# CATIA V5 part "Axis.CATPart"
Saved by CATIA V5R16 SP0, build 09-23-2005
Part number: Axis
Bounding box of the stored display mesh (mm): x -19.5 to 19.5, y 0 to 171, z -19.486 to 19.486
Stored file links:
  C:\V5_education\CATIA Data\ASD\Power Transmission Gear Assembly\Assembly Data\Axis.CATPart
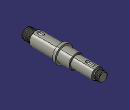
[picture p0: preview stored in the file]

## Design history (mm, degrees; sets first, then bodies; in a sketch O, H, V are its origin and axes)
Set1 "Reference Data"
  Point1 "Center Point": (0, 0, 0)
  Plane1: type Offset, RefPlane zx-plane, Offset 18
  Plane2: type Offset, RefPlane zx-plane, Offset -160, reversed
Body1 (main body)
  Body2
    Sketch1 on yz-plane, origin (0, 0, 0), H (0, 1, 0), V (0, 0, 1)
      line L1 (0, 0) -> (0, 12)
      line L2 (0, 12) -> (18, 12)
      line L3 (18, 12) -> (18, 11)
      line L4 (18, 11) -> (20, 11)
      line L5 (20, 11) -> (20, 15)
      line L6 (20, 15) -> (77, 15)
      line L7 (77, 15) -> (77, 19.5)
      point P7 (77, 19.5)
      line L8 (77, 19.5) -> (83, 19.5)
      line L9 (83, 19.5) -> (83, 15.5)
      line L10 (83, 15.5) -> (111, 15.5)
      line L11 (111, 15.5) -> (111, 12.5)
      line L12 (111, 12.5) -> (158, 12.5)
      line L13 (158, 12.5) -> (158, 9)
      line L14 (158, 9) -> (160, 9)
      line L15 (160, 9) -> (160, 10)
      line L16 (160, 10) -> (171, 10)
      line L17 (171, 10) -> (171, 0)
      point P17 (171, 0)
      axis line L18 (0, 0) -> (171, 0)
      distance L2 H = 12
      distance L18 L4 = 11
      distance L18 L6 = 15
      distance L8 L18 = 19.5
      distance L12 L18 = 12.5
      distance L16 L18 = 10
      distance L17 L13 = 13
      distance L17 L11 = 60
      distance L9 L11 = 28
      distance L9 P7 = 6
      distance L7 L1 = 77
      distance L5 L1 = 20
      distance L5 L3 = 2
      distance L15 L13 = 2
      distance L14 L18 = 9
      distance L10 L18 = 15.5
      vertical: L1 V, L3 V, L5 V, L7 V, L9 V, L11 V, L13 V, L15 V, L17 V
      horizontal: L2 H, L4 H, L6 H, L8 H, L10 H, L12 H, L14 H, L16 H, L18 H
      coincidence: P17 H
    Shaft1: profile Sketch1, axis Sketch1.L18, angle 360
    Chamfer1: length 1, angle 45, on face of Shaft1 from Sketch1.L17; face of Shaft1 from Sketch1.L1
    Body3
      Sketch2 on xy-plane, origin (0, 0, 0), H (0, 1, 0), V (-1, 0, 0)
        construction line L1 (28, 0) -> (35, 0)
        point P1 (28, 0)
        line L2 (28, 4) -> (35, 4)
        line L3 (35, -4) -> (28, -4)
        arc A1 centre (35, 0) radius 4 from (35, 4) to (35, -4) cw
        arc A2 centre (28, 0) radius 4 from (28, -4) to (28, 4) cw
        construction line L4 (135.5, 0) -> (148.5, 0)
        point P7 (135.5, 0)
        line L5 (135.5, 3.5) -> (148.5, 3.5)
        line L6 (148.5, -3.5) -> (135.5, -3.5)
        arc A3 centre (148.5, 0) radius 3.5 from (148.5, 3.5) to (148.5, -3.5) cw
        arc A4 centre (135.5, 0) radius 3.5 from (135.5, -3.5) to (135.5, 3.5) cw
        reference intersected line E1 through (20, 0) direction (0, 1) from face of Shaft1 from Sketch1.L5
        reference intersected line E2 through (111, 0) direction (0, 1) from face of Shaft1 from Sketch1.L11
        distance L1 L2 = 4
        distance L4 L5 = 3.5
        distance A2 E1 = 4
        distance A2 A1 = 15
        distance A4 E2 = 21
        distance A4 A3 = 20
        coincidence: P1 H, P7 H
        horizontal: L1 H, L4 H
        tangency: A1 L2, A2 L2, A1 L3, A2 L3, A3 L5, A4 L5, A3 L6, A4 L6
      Pocket1: profile Sketch2.L3, length 20, opposite side length -11
      Pocket2: profile Sketch2.L6, length 20, opposite side length -8.5
    Assemble1: tool Body3
    Chamfer2: length 1, angle 60, on edge [face of Shaft1 from Sketch1.L2 | face of Shaft1 from Sketch1.L3]
    Chamfer3: length 1, angle 60, on edge [face of Shaft1 from Sketch1.L15 | face of Shaft1 from Sketch1.L16]
    Split1: SplitPlane Plane1
    Split2: SplitPlane Plane2
  Assemble2: tool Body2
  Body4 "M24 Helix Body"
    Sketch3 on yz-plane, origin (0, 0, 0), H (0, 1, 0), V (0, 0, 1)
      line L1 (0, 0) -> (0, 12)
      line L2 (0, 12) -> (18, 12)
      line L3 (18, 12) -> (18, 11)
      line L4 (18, 11) -> (20, 11)
      line L5 (20, 11) -> (20, 15)
      line L6 (20, 15) -> (77, 15)
      line L7 (77, 15) -> (77, 19.5)
      point P7 (77, 19.5)
      line L8 (77, 19.5) -> (83, 19.5)
      line L9 (83, 19.5) -> (83, 15)
      point P9 (83, 15)
      line L10 (83, 15) -> (111, 15)
      line L11 (111, 15) -> (111, 12.5)
      line L12 (111, 12.5) -> (158, 12.5)
      line L13 (158, 12.5) -> (158, 9)
      line L14 (158, 9) -> (160, 9)
      line L15 (160, 9) -> (160, 10)
      line L16 (160, 10) -> (171, 10)
      line L17 (171, 10) -> (171, 0)
      point P17 (171, 0)
      axis line L18 (0, 0) -> (171, 0)
      distance L2 H = 12
      distance L18 L4 = 11
      distance L18 L6 = 15
      distance L8 L18 = 19.5
      distance L12 L18 = 12.5
      distance L16 L18 = 10
      distance L17 L13 = 13
      distance L17 L11 = 60
      distance L9 L11 = 28
      distance L9 P7 = 6
      distance L7 L1 = 77
      distance L5 L1 = 20
      distance L5 L3 = 2
      distance L15 L13 = 2
      distance L14 L18 = 9
      vertical: L1 V, L3 V, L5 V, L7 V, L9 V, L11 V, L13 V, L15 V, L17 V
      horizontal: L2 H, L4 H, L6 H, L8 H, L10 H, L12 H, L14 H, L16 H, L18 H
      coincidence: P9 L6, P17 H
    Shaft2: profile Sketch3, axis Sketch3.L18, angle 360
    Chamfer4: length 1, angle 45, on face of Shaft2 from Sketch3.L17; face of Shaft2 from Sketch3.L1
    Body5
      Sketch4 on xy-plane, origin (0, 0, 0), H (0, 1, 0), V (-1, 0, 0)
        construction line L1 (28, 0) -> (35, 0)
        point P1 (28, 0)
        line L2 (28, 4) -> (35, 4)
        line L3 (35, -4) -> (28, -4)
        arc A1 centre (35, 0) radius 4 from (35, 4) to (35, -4) cw
        arc A2 centre (28, 0) radius 4 from (28, -4) to (28, 4) cw
        construction line L4 (135.5, 0) -> (148.5, 0)
        point P7 (135.5, 0)
        line L5 (135.5, 3.5) -> (148.5, 3.5)
        line L6 (148.5, -3.5) -> (135.5, -3.5)
        arc A3 centre (148.5, 0) radius 3.5 from (148.5, 3.5) to (148.5, -3.5) cw
        arc A4 centre (135.5, 0) radius 3.5 from (135.5, -3.5) to (135.5, 3.5) cw
        reference intersected line E1 through (20, 0) direction (0, 1) from face of Shaft2 from Sketch3.L5
        reference intersected line E2 through (111, 0) direction (0, 1) from face of Shaft2 from Sketch3.L11
        distance L1 L2 = 4
        distance L4 L5 = 3.5
        distance A2 E1 = 4
        distance A2 A1 = 15
        distance A4 E2 = 21
        distance A4 A3 = 20
        coincidence: P1 H, P7 H
        horizontal: L1 H, L4 H
        tangency: A1 L2, A2 L2, A1 L3, A2 L3, A3 L5, A4 L5, A3 L6, A4 L6
      Pocket3: profile Sketch4.L3, length 20, opposite side length -11
      Pocket4: profile Sketch4.L6, length 20, opposite side length -7.5
    Assemble3: tool Body5
    Chamfer5: length 1, angle 60, on edge [face of Shaft2 from Sketch3.L2 | face of Shaft2 from Sketch3.L3]
    Chamfer6: length 1, angle 60, on edge [face of Shaft2 from Sketch3.L15 | face of Shaft2 from Sketch3.L16]
    Split3: SplitPlane Plane1
    Split4: SplitPlane Trim1
    Set2 "M24 Helix Body"
      Point2: (0, -2, 12), relative to Point1
      Line1: type PtDir, RefPoint Point1, Direction zx-plane, Start 0, End 25
      Helix1: Direction Line1, RefPoint Point2, Pitch 2, Height 25, TaperAngle 0
      Sweep1: type Segment, GuideCrv Helix1, Length1 2, Length2 0, Angle 60, DraftDirection zx-plane
      Sweep2: type Segment, GuideCrv Helix1, Length1 2, Length2 0, Angle 60, DraftDirection zx-plane
      Trim1: Trimmed (Sweep1; Sweep2)
  Assemble4: tool Body4
  Body6 "M20 Helix Body"
    Sketch5 on yz-plane, origin (0, 0, 0), H (0, 1, 0), V (0, 0, 1)
      line L1 (0, 0) -> (0, 12)
      line L2 (0, 12) -> (18, 12)
      line L3 (18, 12) -> (18, 11)
      line L4 (18, 11) -> (20, 11)
      line L5 (20, 11) -> (20, 15)
      line L6 (20, 15) -> (77, 15)
      line L7 (77, 15) -> (77, 19.5)
      point P7 (77, 19.5)
      line L8 (77, 19.5) -> (83, 19.5)
      line L9 (83, 19.5) -> (83, 15)
      point P9 (83, 15)
      line L10 (83, 15) -> (111, 15)
      line L11 (111, 15) -> (111, 12.5)
      line L12 (111, 12.5) -> (158, 12.5)
      line L13 (158, 12.5) -> (158, 9)
      line L14 (158, 9) -> (160, 9)
      line L15 (160, 9) -> (160, 10)
      line L16 (160, 10) -> (171, 10)
      line L17 (171, 10) -> (171, 0)
      point P17 (171, 0)
      axis line L18 (0, 0) -> (171, 0)
      distance L2 H = 12
      distance L18 L4 = 11
      distance L18 L6 = 15
      distance L8 L18 = 19.5
      distance L12 L18 = 12.5
      distance L16 L18 = 10
      distance L17 L13 = 13
      distance L17 L11 = 60
      distance L9 L11 = 28
      distance L9 P7 = 6
      distance L7 L1 = 77
      distance L5 L1 = 20
      distance L5 L3 = 2
      distance L15 L13 = 2
      distance L14 L18 = 9
      vertical: L1 V, L3 V, L5 V, L7 V, L9 V, L11 V, L13 V, L15 V, L17 V
      horizontal: L2 H, L4 H, L6 H, L8 H, L10 H, L12 H, L14 H, L16 H, L18 H
      coincidence: P9 L6, P17 H
    Shaft3: profile Sketch5, axis Sketch5.L18, angle 360
    Chamfer7: length 1, angle 45, on face of Shaft3 from Sketch5.L17; face of Shaft3 from Sketch5.L1
    Body7
      Sketch6 on xy-plane, origin (0, 0, 0), H (0, 1, 0), V (-1, 0, 0)
        construction line L1 (28, 0) -> (35, 0)
        point P1 (28, 0)
        line L2 (28, 4) -> (35, 4)
        line L3 (35, -4) -> (28, -4)
        arc A1 centre (35, 0) radius 4 from (35, 4) to (35, -4) cw
        arc A2 centre (28, 0) radius 4 from (28, -4) to (28, 4) cw
        construction line L4 (135.5, 0) -> (148.5, 0)
        point P7 (135.5, 0)
        line L5 (135.5, 3.5) -> (148.5, 3.5)
        line L6 (148.5, -3.5) -> (135.5, -3.5)
        arc A3 centre (148.5, 0) radius 3.5 from (148.5, 3.5) to (148.5, -3.5) cw
        arc A4 centre (135.5, 0) radius 3.5 from (135.5, -3.5) to (135.5, 3.5) cw
        reference intersected line E1 through (20, 0) direction (0, 1) from face of Shaft3 from Sketch5.L5
        reference intersected line E2 through (111, 0) direction (0, 1) from face of Shaft3 from Sketch5.L11
        distance L1 L2 = 4
        distance L4 L5 = 3.5
        distance A2 E1 = 4
        distance A2 A1 = 15
        distance A4 E2 = 21
        distance A4 A3 = 20
        coincidence: P1 H, P7 H
        horizontal: L1 H, L4 H
        tangency: A1 L2, A2 L2, A1 L3, A2 L3, A3 L5, A4 L5, A3 L6, A4 L6
      Pocket5: profile Sketch6.L3, length 20, opposite side length -11
      Pocket6: profile Sketch6.L6, length 20, opposite side length -7.5
    Assemble5: tool Body7
    Chamfer8: length 1, angle 60, on edge [face of Shaft3 from Sketch5.L2 | face of Shaft3 from Sketch5.L3]
    Chamfer9: length 1, angle 60, on edge [face of Shaft3 from Sketch5.L15 | face of Shaft3 from Sketch5.L16]
    Split5: SplitPlane Plane2
    Split6: SplitPlane Trim2
    Set3 "M24 Helix Body"
      Point3: (0, 158, 10), relative to Point1
      Line2: type PtDir, RefPoint Point1, Direction zx-plane, Start 0, End 25
      Helix2: Direction Line2, RefPoint Point3, Pitch 2, Height 25, TaperAngle 0
      Sweep3: type Segment, GuideCrv Helix2, Length1 2, Length2 0, Angle 60, DraftDirection zx-plane
      Sweep4: type Segment, GuideCrv Helix2, Length1 2, Length2 0, Angle 60, DraftDirection zx-plane
      Trim2: Trimmed (Sweep3; Sweep4)
  Assemble6: tool Body6
  Chamfer10: length 1, angle 45, on edge [face of Shaft1 from Sketch1.L5 | face of Shaft1 from Sketch1.L6]; edge [face of Shaft1 from Sketch1.L10 | face of Shaft1 from Sketch1.L11]; edge [face of Shaft1 from Sketch1.L12 | face of Shaft1 from Sketch1.L13]
  Fillet1: radius 0.62, on edge [face of Shaft1 from Sketch1.L6 | face of Shaft1 from Sketch1.L7]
